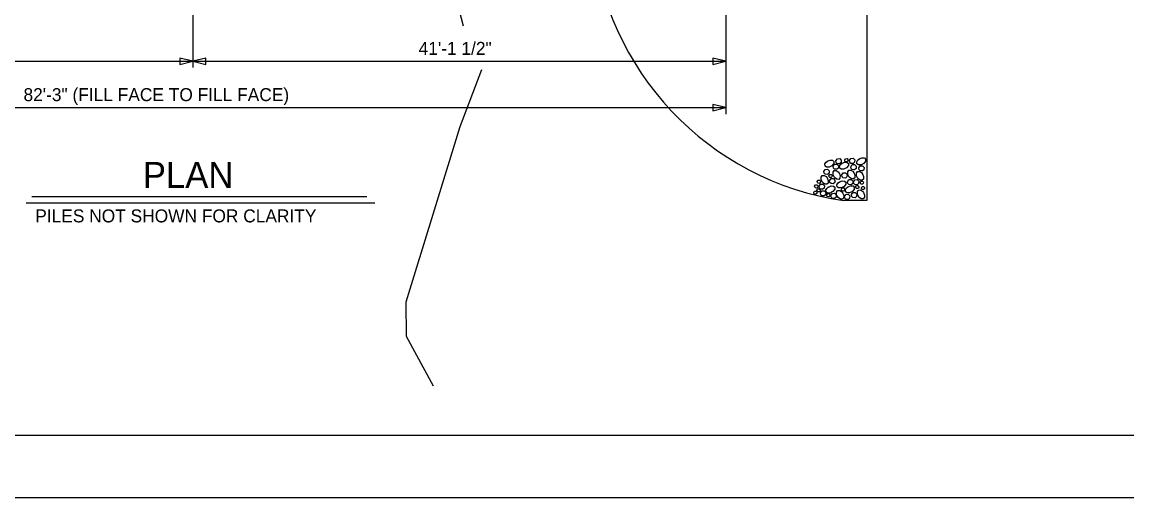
# Model space of a CAD drawing. Extents: x 985 to 1514, y -701 to -21.
# Drawn here: x 1102.9 to 1188.2, y -220.9 to -184.2 of the extents above; entities that cross this region are included whole.
import ezdxf

# ---------------------------------------------------------------- set-up
doc = ezdxf.new("R2010")
doc.units = 0
for name, color, linetype in [('Auto Dimensioning', 7, 'Continuous'), ('Dimension Lines', 7, 'Continuous'), ('Exist Hydro Stream or Body of Water', 7, 'Continuous'), ('Miscellaneous Lines CELL', 7, 'Continuous'), ('Plan Sheet CELL', 7, 'Continuous'), ('Plot Shape CELL', 7, 'Continuous'), ('Sub End Bent Cap Lines CELL', 7, 'Continuous'), ('Sup Concrete Girder Lines', 7, 'Continuous'), ('Text', 7, 'Continuous'), ('Title Text', 7, 'Continuous')]:
    doc.layers.add(name, color=color, linetype=linetype)

# ---------------------------------------------------------------- blocks, each defined once
blk = doc.blocks.new('AH')
at = {"layer": 'Sub End Bent Cap Lines CELL'}
blk.add_lwpolyline([(0, 0), (-1.25, 0.31), (-1.25, -0.31)], close=True, dxfattribs=at)

msp = doc.modelspace()

# ---------------------------------------------------------------- linework, layer by layer
at = {"layer": 'Auto Dimensioning'}
for p, q in [((1157.234, -159.486), (1157.234, -191.32)), ((1075.002, -187.25), (1116.122, -187.25)), ((1116.122, -187.25), (1157.234, -187.25)), ((1075.002, -190.82), (1157.234, -190.82))]:
    msp.add_line(p, q, dxfattribs=at)
at = {"layer": 'Dimension Lines'}
msp.add_line((1116.122, -158.986), (1116.122, -187.723), dxfattribs=at)
at = {"layer": 'Exist Hydro Stream or Body of Water'}
for points in [[(1136.995, -184.536), (1135.256, -177.797), (1136.509, -173.615)], [(1134.691, -212.302), (1132.604, -208.463), (1132.568, -205.785), (1136.734, -192.271), (1138.412, -187.881)]]:
    msp.add_lwpolyline(points, dxfattribs=at)
at = {"layer": 'Miscellaneous Lines CELL'}
for points in [[(1165.069, -194.944), (1165.278, -194.861), (1165.471, -194.877), (1165.562, -194.964), (1165.56, -195.121), (1165.421, -195.298), (1165.206, -195.406), (1165.004, -195.409), (1164.89, -195.328), (1164.879, -195.167), (1164.971, -195.023), (1165.077, -194.939)], [(1165.069, -194.944), (1165.278, -194.861), (1165.471, -194.877), (1165.562, -194.964), (1165.56, -195.121), (1165.421, -195.298), (1165.206, -195.406), (1165.004, -195.409), (1164.89, -195.328), (1164.879, -195.167), (1164.971, -195.023), (1165.077, -194.939)], [(1165.522, -195.345), (1165.634, -195.186), (1165.813, -195.176), (1165.937, -195.304), (1165.919, -195.485), (1165.809, -195.577), (1165.632, -195.564), (1165.549, -195.484), (1165.522, -195.345)], [(1165.522, -195.345), (1165.634, -195.186), (1165.813, -195.176), (1165.937, -195.304), (1165.919, -195.485), (1165.809, -195.577), (1165.632, -195.564), (1165.549, -195.484), (1165.522, -195.345)], [(1165.733, -194.923), (1165.845, -194.764), (1166.024, -194.754), (1166.148, -194.883), (1166.13, -195.064), (1166.019, -195.155), (1165.843, -195.143), (1165.76, -195.062), (1165.733, -194.924)], [(1165.733, -194.923), (1165.845, -194.764), (1166.024, -194.754), (1166.148, -194.883), (1166.13, -195.064), (1166.019, -195.155), (1165.843, -195.143), (1165.76, -195.062), (1165.733, -194.924)], [(1166.208, -195.113), (1166.417, -195.03), (1166.61, -195.047), (1166.701, -195.134), (1166.698, -195.29), (1166.559, -195.468), (1166.345, -195.575), (1166.142, -195.579), (1166.029, -195.498), (1166.018, -195.337), (1166.11, -195.192), (1166.216, -195.108)], [(1166.208, -195.113), (1166.417, -195.03), (1166.61, -195.047), (1166.701, -195.134), (1166.698, -195.29), (1166.559, -195.468), (1166.345, -195.575), (1166.142, -195.579), (1166.029, -195.498), (1166.018, -195.337), (1166.11, -195.192), (1166.216, -195.108)], [(1166.412, -194.858), (1166.48, -194.762), (1166.587, -194.756), (1166.662, -194.834), (1166.651, -194.942), (1166.585, -194.997), (1166.479, -194.989), (1166.429, -194.941), (1166.413, -194.858)], [(1166.412, -194.858), (1166.48, -194.762), (1166.587, -194.756), (1166.662, -194.834), (1166.651, -194.942), (1166.585, -194.997), (1166.479, -194.989), (1166.429, -194.941), (1166.413, -194.858)], [(1166.78, -194.899), (1166.892, -194.74), (1167.071, -194.73), (1167.195, -194.859), (1167.177, -195.039), (1167.066, -195.131), (1166.89, -195.118), (1166.807, -195.038), (1166.78, -194.899)], [(1166.78, -194.899), (1166.892, -194.74), (1167.071, -194.73), (1167.195, -194.859), (1167.177, -195.039), (1167.066, -195.131), (1166.89, -195.118), (1166.807, -195.038), (1166.78, -194.899)], [(1166.885, -195.376), (1166.997, -195.217), (1167.176, -195.207), (1167.3, -195.336), (1167.282, -195.516), (1167.172, -195.608), (1166.995, -195.596), (1166.912, -195.515), (1166.885, -195.376)], [(1166.885, -195.376), (1166.997, -195.217), (1167.176, -195.207), (1167.3, -195.336), (1167.282, -195.516), (1167.172, -195.608), (1166.995, -195.596), (1166.912, -195.515), (1166.885, -195.376)], [(1167.532, -194.772), (1167.741, -194.689), (1167.934, -194.705), (1168.025, -194.792), (1168.022, -194.949), (1167.883, -195.126), (1167.669, -195.233), (1167.467, -195.237), (1167.353, -195.156), (1167.342, -194.995), (1167.434, -194.851), (1167.54, -194.766)], [(1167.532, -194.772), (1167.741, -194.689), (1167.934, -194.705), (1168.025, -194.792), (1168.022, -194.949), (1167.883, -195.126), (1167.669, -195.233), (1167.467, -195.237), (1167.353, -195.156), (1167.342, -194.995), (1167.434, -194.851), (1167.54, -194.766)], [(1165.054, -196.236), (1165.138, -196.446), (1165.121, -196.639), (1165.034, -196.73), (1164.878, -196.727), (1164.7, -196.588), (1164.593, -196.374), (1164.589, -196.171), (1164.67, -196.057), (1164.831, -196.047), (1164.975, -196.139), (1165.06, -196.245)], [(1165.054, -196.236), (1165.138, -196.446), (1165.121, -196.639), (1165.034, -196.73), (1164.878, -196.727), (1164.7, -196.588), (1164.593, -196.374), (1164.589, -196.171), (1164.67, -196.057), (1164.831, -196.047), (1164.975, -196.139), (1165.06, -196.245)], [(1164.803, -195.745), (1164.915, -195.586), (1165.094, -195.575), (1165.219, -195.704), (1165.201, -195.885), (1165.09, -195.977), (1164.913, -195.964), (1164.83, -195.884), (1164.803, -195.745)], [(1164.803, -195.745), (1164.915, -195.586), (1165.094, -195.575), (1165.219, -195.704), (1165.201, -195.885), (1165.09, -195.977), (1164.913, -195.964), (1164.83, -195.884), (1164.803, -195.745)], [(1165.188, -196.072), (1165.256, -195.976), (1165.363, -195.97), (1165.437, -196.047), (1165.427, -196.156), (1165.36, -196.211), (1165.254, -196.203), (1165.205, -196.155), (1165.188, -196.072)], [(1165.188, -196.072), (1165.256, -195.976), (1165.363, -195.97), (1165.437, -196.047), (1165.427, -196.156), (1165.36, -196.211), (1165.254, -196.203), (1165.205, -196.155), (1165.188, -196.072)], [(1165.98, -195.858), (1166.063, -196.067), (1166.046, -196.26), (1165.959, -196.351), (1165.803, -196.348), (1165.625, -196.209), (1165.518, -195.995), (1165.514, -195.793), (1165.595, -195.679), (1165.756, -195.668), (1165.9, -195.76), (1165.985, -195.866)], [(1165.98, -195.858), (1166.063, -196.067), (1166.046, -196.26), (1165.959, -196.351), (1165.803, -196.348), (1165.625, -196.209), (1165.518, -195.995), (1165.514, -195.793), (1165.595, -195.679), (1165.756, -195.668), (1165.9, -195.76), (1165.985, -195.866)], [(1166.181, -196.016), (1166.293, -195.857), (1166.472, -195.847), (1166.596, -195.976), (1166.578, -196.156), (1166.468, -196.248), (1166.291, -196.235), (1166.208, -196.155), (1166.181, -196.016)], [(1166.181, -196.016), (1166.293, -195.857), (1166.472, -195.847), (1166.596, -195.976), (1166.578, -196.156), (1166.468, -196.248), (1166.291, -196.235), (1166.208, -196.155), (1166.181, -196.016)], [(1167.118, -195.83), (1167.201, -196.04), (1167.185, -196.233), (1167.098, -196.324), (1166.942, -196.321), (1166.764, -196.182), (1166.657, -195.968), (1166.653, -195.765), (1166.734, -195.652), (1166.895, -195.641), (1167.039, -195.733), (1167.124, -195.839)], [(1167.118, -195.83), (1167.201, -196.04), (1167.185, -196.233), (1167.098, -196.324), (1166.942, -196.321), (1166.764, -196.182), (1166.657, -195.968), (1166.653, -195.765), (1166.734, -195.652), (1166.895, -195.641), (1167.039, -195.733), (1167.124, -195.839)], [(1167.783, -195.932), (1167.866, -196.142), (1167.849, -196.334), (1167.762, -196.426), (1167.606, -196.423), (1167.428, -196.284), (1167.321, -196.069), (1167.317, -195.867), (1167.398, -195.753), (1167.559, -195.742), (1167.704, -195.835), (1167.788, -195.941)], [(1167.783, -195.932), (1167.866, -196.142), (1167.849, -196.334), (1167.762, -196.426), (1167.606, -196.423), (1167.428, -196.284), (1167.321, -196.069), (1167.317, -195.867), (1167.398, -195.753), (1167.559, -195.742), (1167.704, -195.835), (1167.788, -195.941)], [(1167.498, -195.474), (1167.61, -195.315), (1167.789, -195.304), (1167.913, -195.433), (1167.895, -195.614), (1167.785, -195.706), (1167.608, -195.693), (1167.525, -195.613), (1167.498, -195.474)], [(1167.498, -195.474), (1167.61, -195.315), (1167.789, -195.304), (1167.913, -195.433), (1167.895, -195.614), (1167.785, -195.706), (1167.608, -195.693), (1167.525, -195.613), (1167.498, -195.474)], [(1164.092, -196.882), (1164.16, -196.786), (1164.267, -196.78), (1164.342, -196.857), (1164.331, -196.966), (1164.264, -197.021), (1164.158, -197.013), (1164.109, -196.965), (1164.092, -196.882)], [(1164.092, -196.882), (1164.16, -196.786), (1164.267, -196.78), (1164.342, -196.857), (1164.331, -196.966), (1164.264, -197.021), (1164.158, -197.013), (1164.109, -196.965), (1164.092, -196.882)], [(1164.291, -196.521), (1164.358, -196.425), (1164.465, -196.419), (1164.54, -196.497), (1164.529, -196.605), (1164.463, -196.66), (1164.357, -196.652), (1164.307, -196.604), (1164.291, -196.521)], [(1164.291, -196.521), (1164.358, -196.425), (1164.465, -196.419), (1164.54, -196.497), (1164.529, -196.605), (1164.463, -196.66), (1164.357, -196.652), (1164.307, -196.604), (1164.291, -196.521)], [(1164.437, -196.886), (1164.549, -196.726), (1164.728, -196.716), (1164.852, -196.845), (1164.834, -197.026), (1164.723, -197.118), (1164.547, -197.105), (1164.464, -197.024), (1164.437, -196.886)], [(1164.437, -196.886), (1164.549, -196.726), (1164.728, -196.716), (1164.852, -196.845), (1164.834, -197.026), (1164.723, -197.118), (1164.547, -197.105), (1164.464, -197.024), (1164.437, -196.886)], [(1165.154, -196.944), (1165.364, -196.861), (1165.557, -196.877), (1165.648, -196.964), (1165.645, -197.121), (1165.506, -197.298), (1165.292, -197.405), (1165.089, -197.409), (1164.975, -197.328), (1164.965, -197.167), (1165.057, -197.023), (1165.163, -196.938)], [(1165.154, -196.944), (1165.364, -196.861), (1165.557, -196.877), (1165.648, -196.964), (1165.645, -197.121), (1165.506, -197.298), (1165.292, -197.405), (1165.089, -197.409), (1164.975, -197.328), (1164.965, -197.167), (1165.057, -197.023), (1165.163, -196.938)], [(1165.245, -196.457), (1165.357, -196.297), (1165.536, -196.287), (1165.661, -196.416), (1165.643, -196.597), (1165.532, -196.689), (1165.356, -196.676), (1165.272, -196.595), (1165.245, -196.457)], [(1165.245, -196.457), (1165.357, -196.297), (1165.536, -196.287), (1165.661, -196.416), (1165.643, -196.597), (1165.532, -196.689), (1165.356, -196.676), (1165.272, -196.595), (1165.245, -196.457)], [(1166.004, -196.55), (1166.214, -196.467), (1166.406, -196.484), (1166.498, -196.571), (1166.495, -196.727), (1166.356, -196.905), (1166.141, -197.012), (1165.939, -197.016), (1165.825, -196.935), (1165.814, -196.774), (1165.907, -196.629), (1166.013, -196.545)], [(1166.004, -196.55), (1166.214, -196.467), (1166.406, -196.484), (1166.498, -196.571), (1166.495, -196.727), (1166.356, -196.905), (1166.141, -197.012), (1165.939, -197.016), (1165.825, -196.935), (1165.814, -196.774), (1165.907, -196.629), (1166.013, -196.545)], [(1166.655, -196.925), (1166.864, -196.842), (1167.057, -196.858), (1167.148, -196.945), (1167.145, -197.102), (1167.006, -197.279), (1166.792, -197.386), (1166.589, -197.39), (1166.476, -197.309), (1166.465, -197.148), (1166.557, -197.004), (1166.663, -196.919)], [(1166.655, -196.925), (1166.864, -196.842), (1167.057, -196.858), (1167.148, -196.945), (1167.145, -197.102), (1167.006, -197.279), (1166.792, -197.386), (1166.589, -197.39), (1166.476, -197.309), (1166.465, -197.148), (1166.557, -197.004), (1166.663, -196.919)], [(1166.629, -196.536), (1166.741, -196.376), (1166.92, -196.366), (1167.045, -196.495), (1167.027, -196.676), (1166.916, -196.768), (1166.739, -196.755), (1166.656, -196.674), (1166.629, -196.536)], [(1166.629, -196.536), (1166.741, -196.376), (1166.92, -196.366), (1167.045, -196.495), (1167.027, -196.676), (1166.916, -196.768), (1166.739, -196.755), (1166.656, -196.674), (1166.629, -196.536)], [(1167.09, -196.543), (1167.202, -196.383), (1167.381, -196.373), (1167.505, -196.502), (1167.487, -196.683), (1167.377, -196.774), (1167.2, -196.762), (1167.117, -196.681), (1167.09, -196.543)], [(1167.09, -196.543), (1167.202, -196.383), (1167.381, -196.373), (1167.505, -196.502), (1167.487, -196.683), (1167.377, -196.774), (1167.2, -196.762), (1167.117, -196.681), (1167.09, -196.543)], [(1167.253, -196.928), (1167.32, -196.832), (1167.428, -196.826), (1167.502, -196.904), (1167.492, -197.012), (1167.425, -197.067), (1167.319, -197.06), (1167.269, -197.011), (1167.253, -196.928)], [(1167.253, -196.928), (1167.32, -196.832), (1167.428, -196.826), (1167.502, -196.904), (1167.492, -197.012), (1167.425, -197.067), (1167.319, -197.06), (1167.269, -197.011), (1167.253, -196.928)], [(1167.6, -196.592), (1167.667, -196.496), (1167.775, -196.49), (1167.849, -196.567), (1167.838, -196.676), (1167.772, -196.731), (1167.666, -196.723), (1167.616, -196.675), (1167.6, -196.592)], [(1167.6, -196.592), (1167.667, -196.496), (1167.775, -196.49), (1167.849, -196.567), (1167.838, -196.676), (1167.772, -196.731), (1167.666, -196.723), (1167.616, -196.675), (1167.6, -196.592)], [(1167.695, -197.007), (1167.762, -196.911), (1167.869, -196.905), (1167.944, -196.982), (1167.933, -197.091), (1167.867, -197.146), (1167.761, -197.138), (1167.711, -197.09), (1167.695, -197.007)], [(1167.695, -197.007), (1167.762, -196.911), (1167.869, -196.905), (1167.944, -196.982), (1167.933, -197.091), (1167.867, -197.146), (1167.761, -197.138), (1167.711, -197.09), (1167.695, -197.007)], [(1164.02, -197.362), (1164.088, -197.267), (1164.195, -197.261), (1164.269, -197.338), (1164.259, -197.446), (1164.192, -197.502), (1164.086, -197.494), (1164.037, -197.446), (1164.02, -197.362)], [(1164.02, -197.362), (1164.088, -197.267), (1164.195, -197.261), (1164.269, -197.338), (1164.259, -197.446), (1164.192, -197.502), (1164.086, -197.494), (1164.037, -197.446), (1164.02, -197.362)], [(1164.261, -197.176), (1164.328, -197.08), (1164.435, -197.074), (1164.51, -197.152), (1164.499, -197.26), (1164.433, -197.315), (1164.327, -197.308), (1164.277, -197.259), (1164.261, -197.176)], [(1164.261, -197.176), (1164.328, -197.08), (1164.435, -197.074), (1164.51, -197.152), (1164.499, -197.26), (1164.433, -197.315), (1164.327, -197.308), (1164.277, -197.259), (1164.261, -197.176)], [(1164.533, -197.397), (1164.645, -197.237), (1164.824, -197.227), (1164.948, -197.356), (1164.93, -197.537), (1164.82, -197.629), (1164.643, -197.616), (1164.56, -197.535), (1164.533, -197.397)], [(1164.533, -197.397), (1164.645, -197.237), (1164.824, -197.227), (1164.948, -197.356), (1164.93, -197.537), (1164.82, -197.629), (1164.643, -197.616), (1164.56, -197.535), (1164.533, -197.397)], [(1165.023, -197.555), (1165.091, -197.459), (1165.198, -197.453), (1165.273, -197.53), (1165.262, -197.639), (1165.195, -197.694), (1165.089, -197.686), (1165.04, -197.638), (1165.023, -197.555)], [(1165.023, -197.555), (1165.091, -197.459), (1165.198, -197.453), (1165.273, -197.53), (1165.262, -197.639), (1165.195, -197.694), (1165.089, -197.686), (1165.04, -197.638), (1165.023, -197.555)], [(1165.344, -197.595), (1165.456, -197.436), (1165.635, -197.425), (1165.759, -197.554), (1165.741, -197.735), (1165.63, -197.827), (1165.454, -197.814), (1165.371, -197.734), (1165.344, -197.595)], [(1165.344, -197.595), (1165.456, -197.436), (1165.635, -197.425), (1165.759, -197.554), (1165.741, -197.735), (1165.63, -197.827), (1165.454, -197.814), (1165.371, -197.734), (1165.344, -197.595)], [(1166.25, -197.396), (1166.333, -197.606), (1166.316, -197.799), (1166.229, -197.89), (1166.073, -197.887), (1165.895, -197.748), (1165.788, -197.534), (1165.784, -197.331), (1165.865, -197.217), (1166.027, -197.207), (1166.171, -197.299), (1166.255, -197.405)], [(1166.25, -197.396), (1166.333, -197.606), (1166.316, -197.799), (1166.229, -197.89), (1166.073, -197.887), (1165.895, -197.748), (1165.788, -197.534), (1165.784, -197.331), (1165.865, -197.217), (1166.027, -197.207), (1166.171, -197.299), (1166.255, -197.405)], [(1166.155, -197.112), (1166.222, -197.016), (1166.33, -197.01), (1166.404, -197.088), (1166.393, -197.196), (1166.327, -197.251), (1166.221, -197.243), (1166.171, -197.195), (1166.155, -197.112)], [(1166.155, -197.112), (1166.222, -197.016), (1166.33, -197.01), (1166.404, -197.088), (1166.393, -197.196), (1166.327, -197.251), (1166.221, -197.243), (1166.171, -197.195), (1166.155, -197.112)], [(1166.395, -197.667), (1166.507, -197.508), (1166.686, -197.498), (1166.81, -197.627), (1166.792, -197.807), (1166.682, -197.899), (1166.505, -197.886), (1166.422, -197.806), (1166.395, -197.667)], [(1166.395, -197.667), (1166.507, -197.508), (1166.686, -197.498), (1166.81, -197.627), (1166.792, -197.807), (1166.682, -197.899), (1166.505, -197.886), (1166.422, -197.806), (1166.395, -197.667)], [(1166.929, -197.533), (1167.041, -197.374), (1167.22, -197.364), (1167.344, -197.492), (1167.326, -197.673), (1167.216, -197.765), (1167.039, -197.752), (1166.956, -197.672), (1166.929, -197.533)], [(1166.929, -197.533), (1167.041, -197.374), (1167.22, -197.364), (1167.344, -197.492), (1167.326, -197.673), (1167.216, -197.765), (1167.039, -197.752), (1166.956, -197.672), (1166.929, -197.533)], [(1167.864, -197.362), (1167.947, -197.572), (1167.93, -197.765), (1167.843, -197.856), (1167.687, -197.853), (1167.51, -197.714), (1167.402, -197.5), (1167.399, -197.297), (1167.48, -197.183), (1167.641, -197.173), (1167.785, -197.265), (1167.869, -197.371)], [(1167.864, -197.362), (1167.947, -197.572), (1167.93, -197.765), (1167.843, -197.856), (1167.687, -197.853), (1167.51, -197.714), (1167.402, -197.5), (1167.399, -197.297), (1167.48, -197.183), (1167.641, -197.173), (1167.785, -197.265), (1167.869, -197.371)]]:
    msp.add_lwpolyline(points, dxfattribs=at)
at = {"layer": 'Plan Sheet CELL'}
msp.add_line((1007.154, -216.068), (1263.157, -216.068), dxfattribs=at)
at = {"layer": 'Plot Shape CELL'}
msp.add_lwpolyline([(998.722, -44.917), (1263.227, -44.917), (1263.227, -220.917), (998.722, -220.917)], close=True, dxfattribs=at)
at = {"layer": 'Sup Concrete Girder Lines'}
for p, q in [((1168.122, -177.358), (1168.122, -197.986)), ((1168.122, -197.986), (1166.343, -197.993)), ((1168.122, -197.986), (1166.343, -197.993))]:
    msp.add_line(p, q, dxfattribs=at)
msp.add_arc((1169.597, -175.48), 22.747, 184.92778, 261.77484, dxfattribs=at)
at = {"layer": 'Title Text'}
for p, q in [((1103.698, -197.671), (1129.539, -197.671)), ((1103.248, -198.171), (1130.157, -198.171))]:
    msp.add_line(p, q, dxfattribs=at)

# ---------------------------------------------------------------- block references
at = {"layer": 'Auto Dimensioning', "xscale": 0.8, "yscale": 0.8000000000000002}
for p in [(1116.122, -187.25), (1157.234, -187.25), (1157.234, -190.82)]:
    msp.add_blockref('AH', p, dxfattribs=at)
at = {"layer": 'Auto Dimensioning', "xscale": 0.8, "yscale": 0.8000000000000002, "rotation": 180}
msp.add_blockref('AH', (1116.122, -187.25), dxfattribs=at)

# ---------------------------------------------------------------- texts
at = {"layer": 'Text'}
for s, p in [('41\'-1 1/2"', (1133.535, -186.75)), ('82\'-3" (FILL FACE TO FILL FACE)', (1103.048, -190.32)), ('PILES NOT SHOWN FOR CLARITY', (1103.955, -199.671))]:
    msp.add_text(s, height=1, dxfattribs=at).set_placement(p)
at = {"layer": 'Title Text'}
msp.add_text('PLAN', height=2, dxfattribs=at).set_placement((1112.257, -197.008))

doc.saveas('drawing.dxf')
